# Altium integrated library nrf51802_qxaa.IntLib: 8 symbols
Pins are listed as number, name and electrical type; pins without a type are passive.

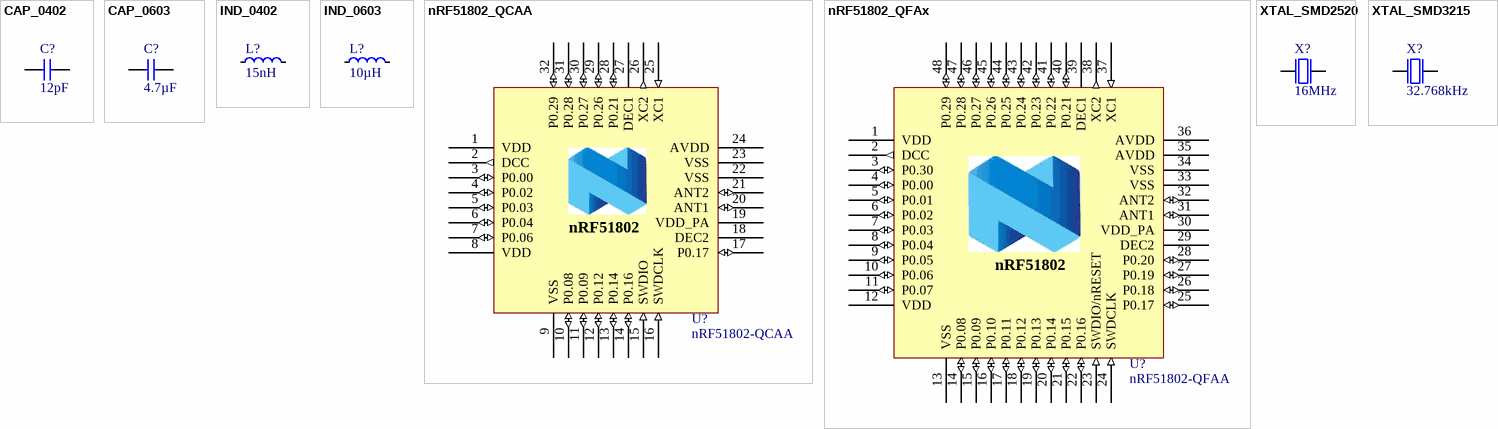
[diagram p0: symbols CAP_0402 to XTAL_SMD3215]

## CAP_0402
designator C?, comment 12pF
Capacitor, NP0, ±2%; Part Number: C0402-12p; Note: 50V; Artikkelnr Noca: 20029159; Artikkelnr Simpro: N.A.
footprint CAPC1005X04L
pins: 1, 2

## CAP_0603
designator C?, comment 4.7µF
Capacitor, X5R, ±10%; Part Number: C0603-4µ7; Note: 6.3V; Artikkelnr Noca: 20069060; Artikkelnr Simpro: N.A.
footprint CAPC1608X06L
pins: 1, 2

## IND_0402
designator L?, comment 15nH
High frequency chip inductor ±10%; Part Number: L0402-15n; Manufacturer: Taiyo Yuden; Manufacturer Part Number: HK100515NJ-T; 2nd source part number: 658-1328; Artikkelnr Noca: 33029323; Artikkelnr Simpro: N.A.
footprint INDC1005X04L
pins: 1, 2

## IND_0603
designator L?, comment 10µH
Chip inductor, IDC,min = 50 mA, ±20%; Part Number: L0603-10µ; Manufacturer: Taiyo Yuden; Manufacturer Part Number: LBMF1608T100K; 2nd source part number: 178-6105; Note: LBMF1608T100K 10µH 80mA 0603; Artikkelnr Noca: 33029314; Artikkelnr Simpro: N.A.
footprint INDC1608X06L
pins: 1, 2

## nRF51802_QCAA
designator U?, comment nRF51802-QCAA
Multi-protocol Bluetooth Low Energy and 2.4GHz proprietary system-on-chip; Manufacturer: Nordic Semiconductor; Note: nRF51802 - QFN32 5x5 0.5mm pitch; Artikkelnr Noca: N.A.
footprint Nordic_QFN50P500X500X90-33N
pins: 1 VDD (power), 2 DCC (out), 3 P0.00 (io), 4 P0.02 (io), 5 P0.03 (io), 6 P0.04 (io), 7 P0.06 (io), 8 VDD (power), 9 VSS (power), 10 P0.08 (io), 11 P0.09 (io), 12 P0.12 (io), 13 P0.14 (io), 14 P0.16 (io), 15 SWDIO (in), 16 SWDCLK (in), 17 P0.17 (io), 18 DEC2 (power), 19 VDD_PA (power), 20 ANT1 (io), 21 ANT2 (io), 22 VSS (power), 23 VSS (power), 24 AVDD (power), 25 XC1 (in), 26 XC2 (out), 27 DEC1 (power), 28 P0.21 (io), 29 P0.26 (io), 30 P0.27 (io), 31 P0.28 (io), 32 P0.29 (io), 33 (power) hidden to GND

## nRF51802_QFAx
designator U?, comment nRF51802-QFAA
Multi-protocol Bluetooth Low Energy and 2.4GHz proprietary system-on-chip; Manufacturer: Nordic Semiconductor; Note: nRF51802 - QFN48 6x6 0.4mm pitch; Artikkelnr Noca: N.A.
footprint QFN40P600X600X90-48N
pins: 1 VDD (power), 2 DCC (out), 3 P0.30 (io), 4 P0.00 (io), 5 P0.01 (io), 6 P0.02 (io), 7 P0.03 (io), 8 P0.04 (io), 9 P0.05 (io), 10 P0.06 (io), 11 P0.07 (io), 12 VDD (power), 13 VSS (power), 14 P0.08 (io), 15 P0.09 (io), 16 P0.10 (io), 17 P0.11 (io), 18 P0.12 (io), 19 P0.13 (io), 20 P0.14 (io), 21 P0.15 (io), 22 P0.16 (io), 23 SWDIO/nRESET (in), 24 SWDCLK (in), 25 P0.17 (io), 26 P0.18 (io), 27 P0.19 (io), 28 P0.20 (io), 29 DEC2 (power), 30 VDD_PA (power), 31 ANT1 (io), 32 ANT2 (io), 33 VSS (power), 34 VSS (power), 35 AVDD (power), 36 AVDD (power), 37 XC1 (in), 38 XC2 (out), 39 DEC1 (power), 40 P0.21 (io), 41 P0.22 (io), 42 P0.23 (io), 43 P0.24 (io), 44 P0.25 (io), 45 P0.26 (io), 46 P0.27 (io), 47 P0.28 (io), 48 P0.29 (io), 49 (power) hidden to GND

## XTAL_SMD2520
designator X?, comment 16MHz
XTAL SMD 2520, 16MHz, 8pF, ±40ppm; Part Number: XTAL_SMD2520_16MHz_8pF_NDK; Manufacturer: NDK; Manufacturer Part Number: NX2520SA/16MHz/EXS00A-CS06713; Note: XTAL SMD 16.000MHz; Artikkelnr Noca: 22019192; Artikkelnr Simpro: N.A.
footprint BT-XTAL_2520
pins: 1 inp, 2 GND hidden to GND, 3 out, 4 GND hidden to GND

## XTAL_SMD3215
designator X?, comment 32.768kHz
XTAL SMD 3215, 32.768kHz, 9pF, ±20ppm; Part Number: XTAL_FC-135 32.768k; Manufacturer: Epson Toyocom; Manufacturer Part Number: FC-135 32.768KHZ ±20PPM,9.0PF; 2nd source part number: 127-8037; Note: XTAL SMD 32.768kHz, 3215; Artikkelnr Noca: 22019091; Artikkelnr Simpro: N.A.
footprint XTAL_3215
pins: 1 inp, 2 out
